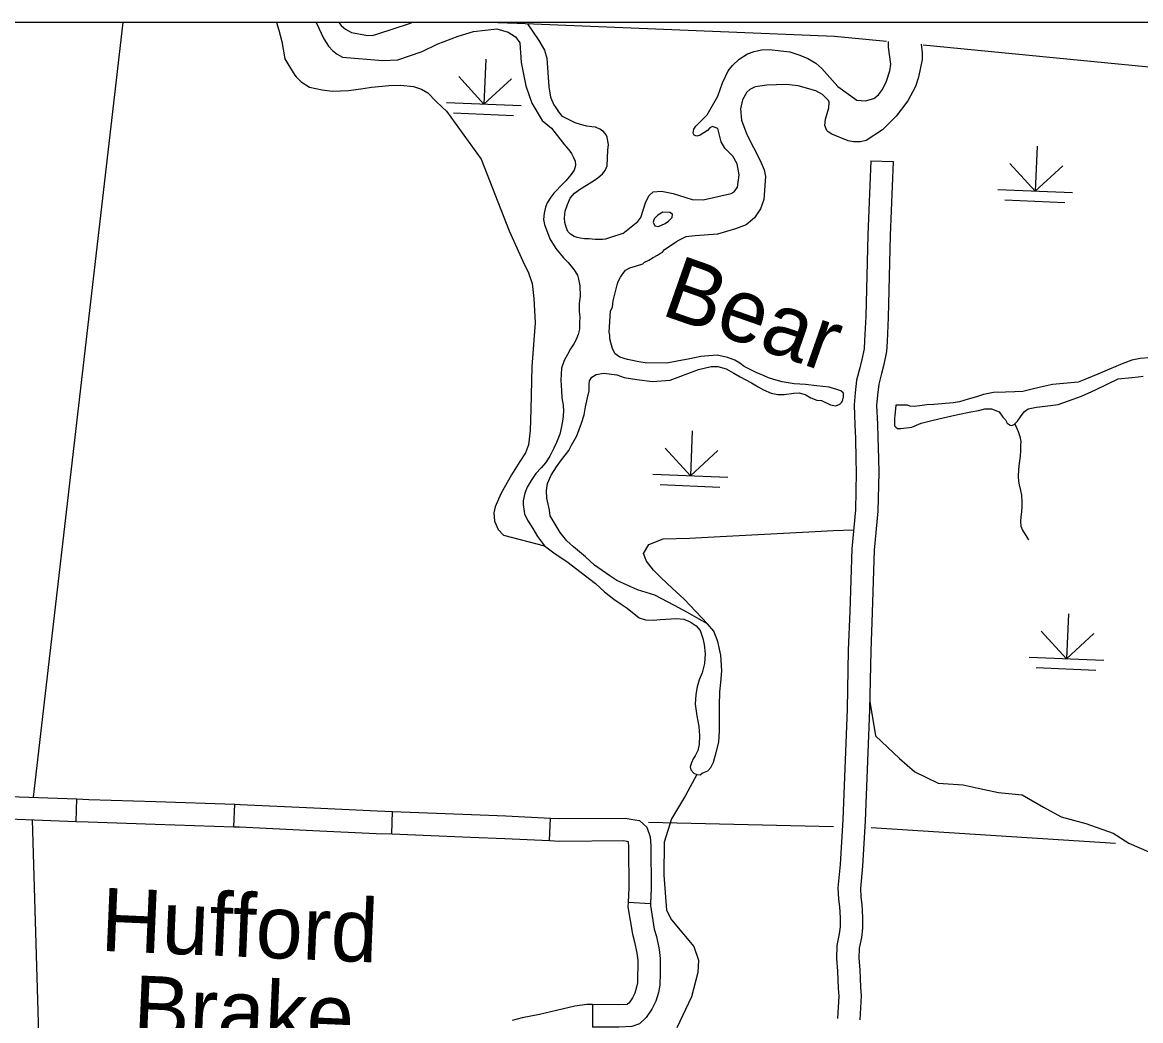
# Model space of a CAD drawing. Extents: x 1196286 to 1268366, y 2040822 to 2082115.
# Drawn here: x 1228738 to 1231542, y 2063093 to 2065597 of the extents above; entities that cross this region are included whole.
import ezdxf

# ---------------------------------------------------------------- set-up
doc = ezdxf.new("R2010")
doc.units = 0
for name, color, linetype in [('55', 7, 'Continuous'), ('60', 7, 'Continuous'), ('62', 7, 'Continuous'), ('Level 69', 7, 'Continuous'), ('Level 72', 7, 'Continuous'), ('Level 73', 7, 'Continuous'), ('Level 74', 7, 'Continuous'), ('Level 8', 7, 'Continuous')]:
    doc.layers.add(name, color=color, linetype=linetype)

msp = doc.modelspace()

# ---------------------------------------------------------------- linework, layer by layer
at = {"layer": '55'}
for points in [[(1229978.4, 2065593.9), (1229905.6, 2065596.8)], [(1230904.6, 2065548.8), (1230774.1, 2065561.5), (1229978.4, 2065593.9)], [(1235980.9, 2065250.1), (1234824.1, 2065276.9), (1232840.2, 2065359.5), (1230996.5, 2065539.8)]]:
    msp.add_lwpolyline(points, dxfattribs=at)
at = {"layer": '60'}
for points in [[(1228989.6, 2065596.8), (1228764.7, 2063653.2)], [(1228762.5, 2063597), (1228790.1, 2062665)], [(1230307.5, 2063591), (1230771.6, 2063580.4)], [(1230865.8, 2063577.3), (1231478.5, 2063537.9)]]:
    msp.add_lwpolyline(points, dxfattribs=at)
at = {"layer": '62'}
for points in [[(1229474.3, 2065596.8), (1229493.6, 2065555.6), (1229505.2, 2065537.3), (1229516.2, 2065525.1), (1229526.9, 2065516.9), (1229540.9, 2065509.5), (1229641.9, 2065501.4), (1229679, 2065503.2), (1229740.5, 2065523.4), (1229778.3, 2065542.5), (1229830.8, 2065562.5), (1229868.9, 2065574.1), (1229927.4, 2065580.8), (1229956.1, 2065572.6), (1229974.2, 2065560.6), (1229985.1, 2065545.7), (1229988.9, 2065496), (1230000.4, 2065437.4), (1230015.3, 2065394.2), (1230040.9, 2065350.4)], [(1229531.6, 2065596.8), (1229537, 2065589.3), (1229548, 2065580.1), (1229563.6, 2065571.8), (1229599.4, 2065564.3), (1229615.9, 2065564), (1229629.4, 2065567.8), (1229708.6, 2065594), (1229714.4, 2065596.8)], [(1230004.8, 2065593.1), (1230033.2, 2065551.5), (1230047.3, 2065527.1), (1230052.8, 2065507), (1230057.7, 2065435.1), (1230062, 2065409.1), (1230070.6, 2065389.7), (1230080.4, 2065375.6)], [(1230243.2, 2065067.1), (1230281.3, 2065097.5), (1230289, 2065107.1), (1230301.4, 2065146.4), (1230309.2, 2065162.8), (1230319.2, 2065171.6), (1230340.2, 2065173.4), (1230369.3, 2065167.5), (1230417.3, 2065152.6), (1230444.6, 2065151.3), (1230515.3, 2065167.8), (1230522.5, 2065171.8), (1230530.6, 2065183.3), (1230535, 2065214.1), (1230530.4, 2065241.6), (1230519.5, 2065261), (1230499, 2065281), (1230490, 2065297.4), (1230481.7, 2065330.3), (1230467.9, 2065335.8), (1230461.9, 2065332.6), (1230456.1, 2065325.9), (1230437.1, 2065313.9), (1230428.8, 2065311.1), (1230422.2, 2065314.2), (1230419.6, 2065319.2), (1230421.4, 2065329.3), (1230426.4, 2065336.7), (1230455.1, 2065365.1), (1230481.5, 2065411.5), (1230493.1, 2065444.8), (1230507.6, 2065474.9), (1230518.7, 2065488.6), (1230535.5, 2065504.1), (1230556.4, 2065517.6), (1230572.6, 2065524), (1230591.4, 2065527.7), (1230610.5, 2065528.8), (1230662.5, 2065522.5), (1230687.4, 2065514.8), (1230707.1, 2065506.1), (1230727, 2065494.4), (1230742.1, 2065480.9), (1230782.4, 2065435.7), (1230830.3, 2065402), (1230852, 2065399.6), (1230873.1, 2065406), (1230884.2, 2065414.8), (1230894.2, 2065428.1), (1230904.4, 2065449.7), (1230912.8, 2065475.5), (1230915.4, 2065492), (1230909.9, 2065534.6), (1230909.7, 2065549.1)], [(1230991.2, 2065541.9), (1230993.9, 2065520), (1230993.9, 2065503.5), (1230985.1, 2065459.7), (1230977.1, 2065436.1), (1230958, 2065399.7), (1230929.1, 2065361.9), (1230894.3, 2065326.9), (1230853.3, 2065300.3), (1230839, 2065296.8), (1230821.8, 2065297.2), (1230808.4, 2065300.1), (1230767.9, 2065316.4), (1230757.9, 2065321.9), (1230754.6, 2065325.7), (1230750.3, 2065337.8), (1230751.4, 2065354.4), (1230759.9, 2065382.4), (1230761, 2065397), (1230759.5, 2065401.2), (1230744.1, 2065415.8), (1230727.5, 2065424.8), (1230683.2, 2065437.4), (1230652.9, 2065441.1), (1230604.2, 2065439.1), (1230574.9, 2065434.8), (1230562, 2065428.7), (1230554.4, 2065421.7), (1230543.5, 2065402.3), (1230538.9, 2065380.2), (1230540.9, 2065351.6), (1230554.4, 2065315.6), (1230587.9, 2065250.6), (1230597.5, 2065226.7), (1230600.9, 2065210.1), (1230597.4, 2065152.2), (1230588.3, 2065129.4), (1230573.2, 2065106.4), (1230553, 2065088.8), (1230526.2, 2065078.8), (1230480.6, 2065065.9), (1230424.7, 2065061.8), (1230401.8, 2065058.5), (1230379.9, 2065048)], [(1230243.2, 2065067.1), (1230212.3, 2065057.5), (1230200.1, 2065053.4), (1230192.3, 2065052.6), (1230187.7, 2065052.3), (1230173.9, 2065052.4), (1230158.9, 2065053.6), (1230147, 2065054), (1230136.9, 2065055.5), (1230128.7, 2065057.6), (1230121.3, 2065060.1), (1230112.5, 2065065.3), (1230105.6, 2065072.6), (1230101.8, 2065082.9), (1230097.7, 2065095.1), (1230097, 2065106.8), (1230098.6, 2065122.9), (1230104.8, 2065140), (1230111.6, 2065155.9), (1230122.5, 2065168.8), (1230137.5, 2065179.2), (1230152.7, 2065188.1), (1230166.1, 2065196.7), (1230180.3, 2065206.4), (1230192.6, 2065216.9), (1230199.2, 2065224.9), (1230204.5, 2065237.2), (1230205.7, 2065275.9), (1230207.3, 2065290.5), (1230204.5, 2065307.9), (1230204.5, 2065308.6), (1230201.7, 2065314.4), (1230194.8, 2065323.2), (1230185.6, 2065328.8), (1230174.6, 2065334.1), (1230166, 2065334.7), (1230152.9, 2065336.6), (1230137.3, 2065340.5), (1230123.6, 2065345.1), (1230091.9, 2065360.4), (1230080.4, 2065375.6)], [(1230040.9, 2065350.4), (1230064.4, 2065331.2), (1230076.6, 2065316.2), (1230085.3, 2065304.6), (1230097.1, 2065289.9), (1230103.3, 2065282.9), (1230110.5, 2065273.7), (1230114.4, 2065267.9), (1230119.7, 2065257.6), (1230123.6, 2065248.8), (1230125.1, 2065237.5), (1230121.7, 2065226.3), (1230113.5, 2065214.5), (1230100.6, 2065199.2), (1230087.1, 2065185.7), (1230077.4, 2065175.1), (1230070.4, 2065168.2), (1230063, 2065158.3), (1230054, 2065144.6), (1230049.5, 2065133.5), (1230046, 2065118.6), (1230044.7, 2065102.1), (1230047, 2065089.6), (1230060.8, 2065053.8), (1230075.4, 2065029.6), (1230094.9, 2065006.1), (1230106.1, 2064994.4), (1230120.6, 2064977.4), (1230129.5, 2064962.8), (1230132.5, 2064952.9), (1230136.1, 2064935.9), (1230136.4, 2064909.9), (1230134.3, 2064891.6), (1230133.7, 2064871.3), (1230135.9, 2064858.1), (1230135.1, 2064843.4), (1230134.5, 2064827.3), (1230131.9, 2064813.8), (1230126.6, 2064801.2), (1230120.3, 2064790.5), (1230112, 2064778), (1230104.8, 2064763.9), (1230096.1, 2064748.4), (1230089.9, 2064729.8), (1230088.2, 2064699.8), (1230089.6, 2064672.6), (1230090.9, 2064654.9), (1230093.7, 2064636.4), (1230094.7, 2064620.6), (1230092.9, 2064601.5), (1230090.1, 2064583.1), (1230085.4, 2064563.7), (1230077.2, 2064542.9), (1230070.8, 2064528.8), (1230060.8, 2064509.2), (1230049.4, 2064492.3), (1230038.5, 2064479.5), (1230025.3, 2064465.2), (1230013.9, 2064447.9), (1230004, 2064431.3), (1229997.9, 2064415.7), (1229993.6, 2064397.1), (1229993.3, 2064387.7), (1229997, 2064364.2), (1230004.4, 2064348.2), (1230017.6, 2064327.8), (1230029.7, 2064307.5)], [(1230366.9, 2065107), (1230368.2, 2065115.6), (1230361.5, 2065120.3), (1230343.6, 2065121), (1230331, 2065113), (1230322.2, 2065103.8), (1230319.8, 2065095.6), (1230323.4, 2065086.5), (1230333.1, 2065085.1), (1230349.7, 2065092.3), (1230358.4, 2065098.2)], [(1230358.4, 2065098.2), (1230366.9, 2065107)], [(1230579.6, 2064718), (1230548.1, 2064733.8), (1230537.1, 2064741.7), (1230523.9, 2064750), (1230506.1, 2064756.6), (1230480.1, 2064762.3), (1230459, 2064760.8), (1230439.1, 2064758.4), (1230411.2, 2064752.9), (1230379.7, 2064747), (1230353.8, 2064742.4), (1230299.3, 2064743.3), (1230284, 2064745), (1230263.6, 2064749.8), (1230255, 2064751.2), (1230235.7, 2064757.1), (1230224, 2064765.3), (1230218.7, 2064776), (1230215.3, 2064787), (1230210.9, 2064803), (1230210.5, 2064812), (1230209.6, 2064820), (1230212.8, 2064872.5), (1230218, 2064883.6), (1230219.2, 2064898.2), (1230223.1, 2064915.4), (1230226.5, 2064928.8), (1230229.1, 2064938.5), (1230232, 2064947.1), (1230237.6, 2064957.4), (1230243.1, 2064966.3), (1230250.1, 2064975.1), (1230261.2, 2064981.5), (1230275.5, 2064985.6), (1230294, 2064991), (1230297.9, 2064995.7), (1230308.6, 2065000.7), (1230319.3, 2065007.1), (1230330.7, 2065013.1), (1230335.3, 2065016), (1230342.9, 2065020.6), (1230348, 2065026.8), (1230379.9, 2065048)], [(1231563, 2064755.2), (1231540.9, 2064753.7), (1231519.4, 2064749.5), (1231495.5, 2064740.1), (1231463.6, 2064726.8), (1231434.8, 2064714.2), (1231401.8, 2064701.4), (1231385.5, 2064694.4), (1231320.8, 2064688.6), (1231290.3, 2064682), (1231266.5, 2064675.7), (1231246.5, 2064671), (1231226.6, 2064669.8), (1231202.6, 2064669.1), (1231172.6, 2064668.2), (1231147.8, 2064663.3), (1231130.3, 2064657.5), (1231109.5, 2064651.4), (1231088, 2064645.3), (1231071.4, 2064642.8), (1231043.3, 2064640), (1231023.4, 2064638.4), (1231005.4, 2064637.8), (1230988.4, 2064635), (1230974.1, 2064633.6), (1230963.3, 2064633.9), (1230957, 2064636.4), (1230928.2, 2064636.9)], [(1230284.2, 2064103.7), (1230300.2, 2064098.7), (1230320.4, 2064097.3), (1230336.9, 2064099), (1230379, 2064101.4), (1230396.1, 2064099.8), (1230412.4, 2064093.6), (1230427.1, 2064083.3), (1230437.2, 2064071.4), (1230443.7, 2064051.2), (1230447.3, 2064036.4), (1230450.3, 2064013), (1230448.4, 2063988.6), (1230442.1, 2063965.5), (1230435.2, 2063947.7), (1230429.7, 2063930.6), (1230426.5, 2063911.1), (1230425, 2063886.7), (1230428.9, 2063857.3), (1230433.7, 2063830.8), (1230436, 2063807.8), (1230434.9, 2063785.6), (1230431.4, 2063770.7), (1230424.6, 2063757.4), (1230419.9, 2063750), (1230415.5, 2063740), (1230412.5, 2063729.9), (1230413.8, 2063722.4), (1230421.8, 2063714.2), (1230428.8, 2063710.6), (1230437.4, 2063709.9), (1230442.3, 2063713.5), (1230448.4, 2063716.4), (1230456.8, 2063719.8), (1230463.8, 2063727.9), (1230470.6, 2063741.6), (1230477.7, 2063765.8), (1230483.8, 2063791.6), (1230486.2, 2063819.7), (1230485.7, 2063853.6), (1230485.5, 2063883.3), (1230487, 2063917.4), (1230489.3, 2063941.4), (1230491.7, 2063970.7), (1230489.2, 2064009.9), (1230481.7, 2064044.4), (1230472, 2064069.9), (1230455.7, 2064088.1), (1230435.1, 2064099.6), (1230405.3, 2064116.8), (1230373.3, 2064134), (1230323.9, 2064160), (1230280.1, 2064173.8), (1230228.4, 2064196.9), (1230211.2, 2064208.8), (1230172.3, 2064235.2), (1230150.2, 2064256.6), (1230119.9, 2064281.3), (1230103.1, 2064296.1), (1230086.6, 2064317.7), (1230061.3, 2064358.8), (1230059.5, 2064373.1), (1230053.3, 2064403.4), (1230052, 2064422.3), (1230054.5, 2064439.9), (1230063.8, 2064461), (1230076.8, 2064482), (1230090.1, 2064500), (1230108.1, 2064523.1), (1230115.2, 2064536.8), (1230128.3, 2064559.7), (1230140.2, 2064591.3), (1230146.8, 2064612.1), (1230150.1, 2064632.3), (1230155.3, 2064655.1), (1230159.2, 2064673), (1230159.2, 2064684.3), (1230159.4, 2064689.6), (1230159.6, 2064697.5), (1230165.9, 2064707), (1230177, 2064713.8), (1230195.5, 2064717), (1230228.3, 2064712.5), (1230246.8, 2064705.9), (1230278.9, 2064700.8), (1230317.5, 2064696), (1230362.5, 2064699.8), (1230433.5, 2064726.2), (1230464.8, 2064733.8), (1230481.3, 2064733.7), (1230502.8, 2064727.7), (1230522.1, 2064716.7), (1230537.5, 2064707.7), (1230566.1, 2064692.9)], [(1230672, 2064666.7), (1230685.5, 2064667.4), (1230700.7, 2064663.5), (1230714.7, 2064655.2), (1230729.5, 2064649.4), (1230741.8, 2064648.3), (1230763.9, 2064637.4), (1230772.1, 2064635.6), (1230777.7, 2064634.7), (1230787.2, 2064639.3), (1230792.2, 2064644), (1230795.1, 2064650.3), (1230796.8, 2064657.4), (1230796.4, 2064667.2), (1230789.8, 2064672.3), (1230779.8, 2064676.4), (1230761.2, 2064681.9), (1230729.1, 2064685.2), (1230701.1, 2064688.7), (1230673.1, 2064690.4), (1230642.9, 2064695.5), (1230622.1, 2064701.4), (1230608.8, 2064705.6), (1230590, 2064713.7), (1230579.6, 2064718)], [(1230928.2, 2064636.9), (1230927.1, 2064627.2), (1230926.1, 2064619.7), (1230925.1, 2064610.7), (1230924.5, 2064604), (1230924.7, 2064597.6), (1230924.5, 2064590.8), (1230925, 2064585.1), (1230927.9, 2064581.7), (1230931.9, 2064578.1), (1230940.9, 2064577.9), (1230968, 2064581.9), (1230991.5, 2064591.6), (1231021.7, 2064599.3), (1231047, 2064605.3), (1231083.2, 2064613.5), (1231116, 2064620), (1231135.3, 2064623.5), (1231151.5, 2064627.8), (1231167.6, 2064627.7), (1231187.2, 2064619.9), (1231196.5, 2064606.5), (1231202.7, 2064599.9), (1231206.9, 2064591.5), (1231215, 2064586.3), (1231218.7, 2064585.8), (1231224.4, 2064587.9), (1231233.3, 2064596.6), (1231242.3, 2064610.2), (1231250.5, 2064620.5), (1231260.1, 2064627.3), (1231280.5, 2064631.6), (1231302.7, 2064634.6), (1231335, 2064638.8), (1231360.8, 2064647.8), (1231393.7, 2064659.5), (1231428.7, 2064674.9), (1231485.3, 2064702.4), (1231519.9, 2064706.2), (1231535.3, 2064707.6), (1231548.1, 2064709.1)], [(1230566.1, 2064692.9), (1230583, 2064682.4), (1230596.2, 2064674.8), (1230615.8, 2064667), (1230632.5, 2064663.1), (1230648.3, 2064663.7), (1230672, 2064666.7)], [(1231226.1, 2064589.5), (1231234.3, 2064570.3), (1231238.8, 2064558.1), (1231241, 2064545.2), (1231240.7, 2064536.6), (1231240.7, 2064521.9), (1231239.5, 2064508.8), (1231237.1, 2064491.6), (1231235.8, 2064475.1), (1231234.9, 2064457.8), (1231235.2, 2064445.8), (1231236.8, 2064436.7), (1231240.5, 2064422.3), (1231242.8, 2064410.9), (1231244.1, 2064393.9), (1231244.1, 2064383), (1231242.9, 2064369.5), (1231241, 2064356.8), (1231240.3, 2064344.8), (1231241, 2064333.1), (1231245.6, 2064323.6), (1231252, 2064312.1), (1231260.9, 2064299)], [(1230029.7, 2064307.5), (1230047.3, 2064283.6), (1230074, 2064263.6), (1230103, 2064244.6), (1230175, 2064189.3), (1230197.6, 2064168.2), (1230220.6, 2064150.2), (1230238.9, 2064137.9), (1230254, 2064128), (1230284.2, 2064103.7)], [(1230428.8, 2063710.6), (1230400.2, 2063657.4), (1230365.7, 2063599.4), (1230347.2, 2063540.8), (1230346.3, 2063458), (1230353.2, 2063369.8), (1230365.6, 2063346), (1230421.3, 2063279), (1230433.2, 2063244.9), (1230431.9, 2063213.9), (1230415.9, 2063152.5), (1230378.6, 2063074.8)]]:
    msp.add_lwpolyline(points, dxfattribs=at)
at = {"layer": 'Level 69'}
for p, q in [((1228872.7, 2063592.9), (1228874.8, 2063649.1)), ((1229268.6, 2063579.6), (1229270.4, 2063635.9)), ((1229664, 2063561.3), (1229666.2, 2063617.5)), ((1230059.4, 2063544.7), (1230062.1, 2063600.9)), ((1230256.6, 2063390.4), (1230312.8, 2063387.2)), ((1230167.6, 2063133.3), (1230167.2, 2063077.1))]:
    msp.add_line(p, q, dxfattribs=at)
for points in [[(1228676.3, 2063655.9), (1228705.5, 2063655.4), (1228874.8, 2063649.1)], [(1228874.8, 2063649.1), (1228904.7, 2063648), (1229072.6, 2063642.4)], [(1229072.6, 2063642.4), (1229270.4, 2063635.9)], [(1229270.4, 2063635.9), (1229284.2, 2063635.4), (1229468.6, 2063626.6)], [(1229468.6, 2063626.6), (1229627.6, 2063619), (1229666.2, 2063617.5)], [(1229666.2, 2063617.5), (1229864, 2063609.8)], [(1228675.4, 2063599.6), (1228704, 2063599.2), (1228872.7, 2063592.9)], [(1228872.7, 2063592.9), (1228902.7, 2063591.8), (1229070.7, 2063586.2)], [(1229864, 2063609.8), (1229950.5, 2063606.4), (1230062.1, 2063600.9)], [(1230062.1, 2063600.9), (1230085.6, 2063599.8), (1230250.3, 2063600.9), (1230263.3, 2063598.7)], [(1230263.3, 2063598.7), (1230285.3, 2063595), (1230303.7, 2063578.3), (1230312, 2063554.2), (1230314.1, 2063531.2), (1230314.9, 2063424.5), (1230312.8, 2063387.2)], [(1229070.7, 2063586.2), (1229268.6, 2063579.6)], [(1229268.6, 2063579.6), (1229282, 2063579.2), (1229466, 2063570.4)], [(1229466, 2063570.4), (1229625.2, 2063562.8), (1229664, 2063561.3)], [(1229664, 2063561.3), (1229861.8, 2063553.6)], [(1229861.8, 2063553.6), (1229948, 2063550.2), (1230059.4, 2063544.7)], [(1230059.4, 2063544.7), (1230084.4, 2063543.5), (1230245.7, 2063544.6), (1230253.8, 2063543.2)], [(1230253.8, 2063543.2), (1230256.4, 2063542.8), (1230256.6, 2063542.4), (1230257.8, 2063528.4), (1230258.6, 2063425.9), (1230256.6, 2063390.4)], [(1230256.6, 2063390.4), (1230255.9, 2063378.6), (1230267.4, 2063309.6), (1230273, 2063290.6), (1230278.7, 2063262.3), (1230281.1, 2063245), (1230281.2, 2063228.9), (1230280.4, 2063204.3), (1230280.1, 2063194.2)], [(1230312.8, 2063387.2), (1230312.5, 2063381.7), (1230322.4, 2063322.2), (1230327.6, 2063304), (1230334.2, 2063271.7), (1230337.3, 2063249), (1230337.5, 2063228.2), (1230336.7, 2063202.5), (1230336.4, 2063192.4)], [(1230280.1, 2063194.2), (1230279.9, 2063188.3), (1230277.9, 2063176.9), (1230273.5, 2063162), (1230267.9, 2063150.5), (1230259, 2063137.8), (1230255.2, 2063134.2), (1230254.4, 2063133.9), (1230232.2, 2063132.8), (1230167.6, 2063133.3)], [(1230336.4, 2063192.4), (1230336, 2063182.4), (1230332.7, 2063163.9), (1230326.1, 2063141.6), (1230316.5, 2063121.9), (1230301.8, 2063100.8), (1230285.5, 2063085.5), (1230265.9, 2063078.2), (1230233.4, 2063076.5), (1230167.2, 2063077.1)], [(1230167.6, 2063133.3), (1230153.3, 2063133.4), (1230123.1, 2063129), (1230077.3, 2063118.8), (1230034.8, 2063108.7), (1229991.1, 2063100.5), (1229965.8, 2063093.1)]]:
    msp.add_lwpolyline(points, dxfattribs=at)
at = {"layer": 'Level 72'}
for points in [[(1230865.2, 2065249.9), (1230857.8, 2065063.8), (1230852.4, 2064858.7), (1230849.8, 2064799.3), (1230848.8, 2064778.4), (1230842.8, 2064751.1), (1230837.7, 2064730.1), (1230829.6, 2064699.6), (1230826.2, 2064667.4), (1230823.2, 2064637.5), (1230825.5, 2064586.7), (1230826.7, 2064553.8), (1230828, 2064501.3), (1230828.8, 2064467.8), (1230826.5, 2064374.2), (1230817.8, 2064276.1), (1230812.5, 2064119.2), (1230808.6, 2064022.4), (1230805.8, 2063874.4), (1230794.8, 2063597.3), (1230788.3, 2063485.1), (1230782.9, 2063425.9), (1230784.1, 2063397.5), (1230786.6, 2063378.9), (1230787.6, 2063366.4), (1230788.1, 2063349.8), (1230788.1, 2063328.3), (1230785.9, 2063310.7), (1230780.3, 2063281.4), (1230779.3, 2063248.8), (1230781.4, 2063217.5), (1230782.5, 2063196.3), (1230783, 2063173.9), (1230784.8, 2063154.3), (1230781.3, 2063098.8)], [(1230921.4, 2065247.7), (1230914, 2065062), (1230908.6, 2064856.7), (1230905.9, 2064796.7), (1230904.7, 2064771), (1230897.6, 2064738.6), (1230892.3, 2064716.3), (1230885.1, 2064689.4), (1230882.1, 2064661.6), (1230879.6, 2064636), (1230881.7, 2064589), (1230882.9, 2064555.5), (1230884.2, 2064502.7), (1230885, 2064467.7), (1230882.7, 2064371.1), (1230874, 2064272.7), (1230868.7, 2064117.1), (1230864.9, 2064020.8), (1230862.1, 2063872.7), (1230851, 2063594.6), (1230844.4, 2063480.9), (1230839.3, 2063424.6), (1230840.2, 2063402.5), (1230842.6, 2063384.8), (1230843.8, 2063369.4), (1230844.4, 2063350.7), (1230844.4, 2063324.8), (1230841.5, 2063301.9), (1230836.4, 2063275.2), (1230835.6, 2063249.8), (1230837.5, 2063220.9), (1230838.7, 2063198.4), (1230839.2, 2063177.1), (1230841.2, 2063155.2), (1230837.4, 2063095.2)], [(1230865.2, 2065249.9), (1230921.4, 2065247.7)]]:
    msp.add_lwpolyline(points, dxfattribs=at)
at = {"layer": 'Level 73'}
for p, q in [((1229900.1, 2065504.4), (1229895.3, 2065392)), ((1229895.3, 2065392), (1229831.9, 2065461)), ((1229895.3, 2065392), (1229964.4, 2065455.4)), ((1229801.7, 2065396), (1229989, 2065388)), ((1229819.3, 2065369.7), (1229969.2, 2065363.2)), ((1231282.4, 2065286.1), (1231277.6, 2065173.7)), ((1231277.6, 2065173.7), (1231214.2, 2065242.8)), ((1231277.6, 2065173.7), (1231346.6, 2065237.1)), ((1231183.9, 2065177.7), (1231371.2, 2065169.7)), ((1231201.6, 2065151.4), (1231351.4, 2065145)), ((1230417.6, 2064572.3), (1230412.8, 2064459.9)), ((1230412.8, 2064459.9), (1230349.4, 2064528.9)), ((1230412.8, 2064459.9), (1230481.9, 2064523.3)), ((1230319.1, 2064463.9), (1230506.5, 2064455.9)), ((1230336.8, 2064437.6), (1230486.6, 2064431.1)), ((1231360.6, 2064113.2), (1231355.7, 2064000.8)), ((1231355.7, 2064000.8), (1231292.4, 2064069.9)), ((1231355.7, 2064000.8), (1231424.8, 2064064.2)), ((1231262.1, 2064004.8), (1231449.4, 2063996.8)), ((1231279.7, 2063978.5), (1231429.6, 2063972.1))]:
    msp.add_line(p, q, dxfattribs=at)
at = {"layer": 'Level 74'}
for points in [[(1229374.8, 2065596.8), (1229380.9, 2065577.1), (1229388.6, 2065549.1), (1229396.3, 2065505.5), (1229408.7, 2065484.8), (1229421.2, 2065464), (1229424.4, 2065459.8), (1229436.8, 2065447.4), (1229457.7, 2065434.7), (1229489.7, 2065427.6), (1229515.8, 2065424.1), (1229556, 2065426.2), (1229592.1, 2065430.7), (1229613.2, 2065434.5), (1229640.2, 2065437), (1229657.1, 2065438.4), (1229686, 2065439.3), (1229718.8, 2065435.6), (1229738.8, 2065429), (1229754.3, 2065419.8), (1229775, 2065398.8), (1229790.2, 2065384.4), (1229801.5, 2065373.9), (1229888, 2065253.8), (1229958.7, 2065074), (1229993, 2064997.7), (1230006.6, 2064968.3), (1230016.3, 2064942), (1230020.7, 2064903.9), (1230023.7, 2064843.6), (1230015.3, 2064734.1), (1230013, 2064625.9), (1230011.3, 2064573.3), (1230007.2, 2064537.3), (1229999.8, 2064517.6), (1229985.6, 2064495.1), (1229964.4, 2064461.6), (1229938.6, 2064416.1), (1229931.7, 2064400.9), (1229923.3, 2064382), (1229919.8, 2064366.7), (1229922.1, 2064345.6), (1229931.2, 2064324.6), (1229944.2, 2064310.3), (1230047.3, 2064283.6)], [(1230455.7, 2064088.1), (1230397, 2064150.5), (1230367.5, 2064177.4), (1230339.5, 2064203.9), (1230320.3, 2064222.9), (1230303, 2064245.7), (1230295.4, 2064265.1), (1230308.5, 2064287.6), (1230344.5, 2064301.1), (1230410.5, 2064303.5), (1230487.4, 2064307.4), (1230725.6, 2064320), (1230771, 2064322)], [(1230771, 2064322), (1230822.1, 2064324.1)], [(1230862.5, 2063893.7), (1230877.2, 2063807.8), (1230937.5, 2063750.2), (1230975.8, 2063717), (1231034.1, 2063688.8), (1231096.9, 2063684.2), (1231134.4, 2063675.8), (1231185, 2063665.5), (1231244.4, 2063659.1), (1231298.1, 2063628.4), (1231342.7, 2063604), (1231404.3, 2063587.7), (1231472.5, 2063563.7), (1231512.1, 2063538.4), (1231562, 2063516.5)]]:
    msp.add_lwpolyline(points, dxfattribs=at)
at = {"layer": 'Level 8'}
msp.add_lwpolyline([(1241590.6, 2065596.8), (1214332.8, 2065596.8), (1214332.8, 2047966.3), (1241590.6, 2047966.3)], close=True, dxfattribs=at)

# ---------------------------------------------------------------- texts
at = {"layer": '62'}
for s, rotation, p in [('Bear', 340.6754, (1230335.4, 2064864.9)), ('Hufford', 357.548, (1228932.4, 2063268.4)), ('Brake', 357.548, (1229013.4, 2063048.6))]:
    msp.add_text(s, height=158.4, rotation=rotation, dxfattribs=at).set_placement(p)

doc.saveas('drawing.dxf')
